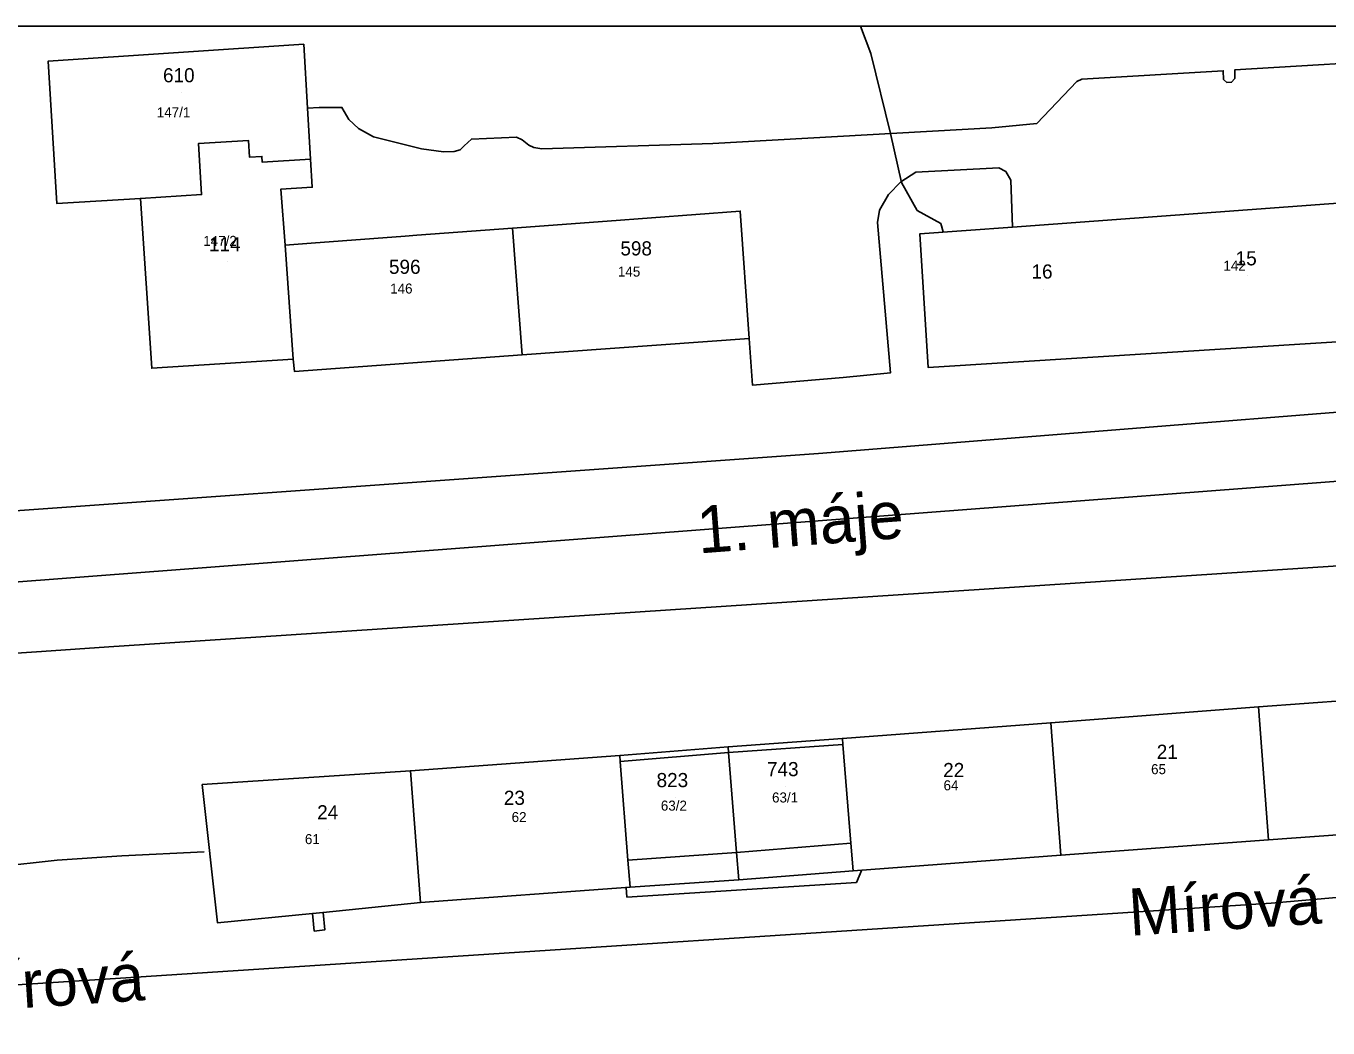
# Model space of a CAD drawing. Extents: x -873642 to -872917, y -1012962 to -1012567.
# Drawn here: x -873283.8 to -873173.4, y -1012652.4 to -1012567.5 of the extents above; entities that cross this region are included whole.
import ezdxf

# ---------------------------------------------------------------- set-up
doc = ezdxf.new("R2010")
doc.units = 0
for name, color, linetype in [('adresni_misto', 7, 'Continuous'), ('cisla_parcelni_kn', 7, 'Continuous'), ('cislo_domovni', 7, 'Continuous'), ('osy_ulic', 7, 'Continuous'), ('parcely_kn', 7, 'Continuous'), ('stavebni_objekty_bydleni', 7, 'Continuous'), ('TRASY - zamereno', 7, 'Continuous'), ('ulice', 7, 'Continuous')]:
    doc.layers.add(name, color=color, linetype=linetype)

msp = doc.modelspace()

# ---------------------------------------------------------------- linework, layer by layer
at = {"layer": 'adresni_misto'}
for p, q in [((-873270.54, -1012573.17), (-873270.54, -1012573.17)), ((-873266.64, -1012587.5), (-873266.64, -1012587.5)), ((-873231.76, -1012587.85), (-873231.76, -1012587.85)), ((-873180.19, -1012588.69), (-873180.19, -1012588.69)), ((-873251.38, -1012589.41), (-873251.38, -1012589.41)), ((-873197.5, -1012589.81), (-873197.5, -1012589.81)), ((-873186.88, -1012630.53), (-873186.88, -1012630.53)), ((-873228.69, -1012632.93), (-873228.69, -1012632.93)), ((-873219.33, -1012632), (-873219.33, -1012632)), ((-873204.99, -1012632.08), (-873204.99, -1012632.08)), ((-873242.24, -1012634.43), (-873242.24, -1012634.43)), ((-873258.07, -1012635.66), (-873258.07, -1012635.66))]:
    msp.add_line(p, q, dxfattribs=at)
at = {"layer": 'osy_ulic'}
for points in [[(-872916.93, -1012586.66), (-872957.62, -1012590.24), (-872977.73, -1012591.46), (-872994.83, -1012592.51), (-873031.96, -1012595.34), (-873059.56, -1012597.3), (-873096.52, -1012600.28), (-873281.07, -1012614.36), (-873481.95, -1012629.68)], [(-873478.28, -1012662.13), (-873469.53, -1012661.58), (-873334.68, -1012652.02), (-873276.17, -1012648.25), (-873178.17, -1012641.86), (-873066.08, -1012632.13)]]:
    msp.add_lwpolyline(points, dxfattribs=at)
at = {"layer": 'parcely_kn'}
msp.add_line((-873158.58, -1012567.5), (-873319.68, -1012567.5), dxfattribs=at)
msp.add_line((-873158.58, -1012567.5), (-873319.68, -1012567.5), dxfattribs=at)
for points in [[(-873259.63, -1012578.8), (-873263.72, -1012579.05), (-873263.76, -1012578.55), (-873264.81, -1012578.61), (-873264.9, -1012577.19), (-873269.13, -1012577.45), (-873268.87, -1012581.79), (-873274.05, -1012582.11), (-873281.15, -1012582.54), (-873281.88, -1012570.48), (-873260.21, -1012569.04), (-873259.89, -1012574.46)], [(-873259.63, -1012578.8), (-873263.72, -1012579.05), (-873263.76, -1012578.55), (-873264.81, -1012578.61), (-873264.9, -1012577.19), (-873269.13, -1012577.45), (-873268.87, -1012581.79), (-873274.05, -1012582.11), (-873281.15, -1012582.54), (-873281.88, -1012570.48), (-873260.21, -1012569.04), (-873259.89, -1012574.46)], [(-873259.63, -1012578.8), (-873259.49, -1012581.17), (-873262.15, -1012581.33), (-873261.79, -1012586.08), (-873261.11, -1012595.73), (-873273.1, -1012596.52), (-873274.05, -1012582.11), (-873268.87, -1012581.79), (-873269.13, -1012577.45), (-873264.9, -1012577.19), (-873264.81, -1012578.61), (-873263.76, -1012578.55), (-873263.72, -1012579.05)], [(-873259.63, -1012578.8), (-873259.49, -1012581.17), (-873262.15, -1012581.33), (-873261.79, -1012586.08), (-873261.11, -1012595.73), (-873273.1, -1012596.52), (-873274.05, -1012582.11), (-873268.87, -1012581.79), (-873269.13, -1012577.45), (-873264.9, -1012577.19), (-873264.81, -1012578.61), (-873263.76, -1012578.55), (-873263.72, -1012579.05)], [(-873155.02, -1012581.21), (-873154.13, -1012593.11), (-873207.27, -1012596.44), (-873207.98, -1012585.12), (-873200.1, -1012584.54), (-873162.95, -1012581.8)], [(-873155.02, -1012581.21), (-873154.13, -1012593.11), (-873207.27, -1012596.44), (-873207.98, -1012585.12), (-873200.1, -1012584.54), (-873162.95, -1012581.8)], [(-873242.5, -1012584.64), (-873234.47, -1012584.03), (-873223.19, -1012583.19), (-873222.44, -1012593.98), (-873241.69, -1012595.39)], [(-873242.5, -1012584.64), (-873234.47, -1012584.03), (-873223.19, -1012583.19), (-873222.44, -1012593.98), (-873241.69, -1012595.39)], [(-873261.79, -1012586.08), (-873259.58, -1012585.91), (-873251.62, -1012585.32), (-873250.61, -1012585.24), (-873242.5, -1012584.64), (-873241.69, -1012595.39), (-873260.98, -1012596.8), (-873261.11, -1012595.73)], [(-873261.79, -1012586.08), (-873259.58, -1012585.91), (-873251.62, -1012585.32), (-873250.61, -1012585.24), (-873242.5, -1012584.64), (-873241.69, -1012595.39), (-873260.98, -1012596.8), (-873261.11, -1012595.73)], [(-873169.13, -1012635.82), (-873169.03, -1012637.22), (-873170.1, -1012637.3), (-873170.2, -1012635.91), (-873178.41, -1012636.51), (-873179.26, -1012625.23), (-873171.5, -1012624.65), (-873171.53, -1012624.2), (-873169.44, -1012624.04), (-873169.41, -1012624.49), (-873161.65, -1012623.9), (-873160.8, -1012635.21)], [(-873169.13, -1012635.82), (-873169.03, -1012637.22), (-873170.1, -1012637.3), (-873170.2, -1012635.91), (-873178.41, -1012636.51), (-873179.26, -1012625.23), (-873171.5, -1012624.65), (-873171.53, -1012624.2), (-873169.44, -1012624.04), (-873169.41, -1012624.49), (-873161.65, -1012623.9), (-873160.8, -1012635.21)], [(-873196.87, -1012626.57), (-873179.26, -1012625.23), (-873178.41, -1012636.51), (-873196.01, -1012637.81)], [(-873196.87, -1012626.57), (-873179.26, -1012625.23), (-873178.41, -1012636.51), (-873196.01, -1012637.81)], [(-873214.53, -1012627.9), (-873196.87, -1012626.57), (-873196.01, -1012637.81), (-873213.62, -1012639.12), (-873213.81, -1012636.78), (-873214.49, -1012628.4)], [(-873214.53, -1012627.9), (-873196.87, -1012626.57), (-873196.01, -1012637.81), (-873213.62, -1012639.12), (-873213.81, -1012636.78), (-873214.49, -1012628.4)], [(-873213.62, -1012639.12), (-873223.33, -1012639.88), (-873223.51, -1012637.58), (-873224.18, -1012629.09), (-873224.21, -1012628.62), (-873214.53, -1012627.9), (-873214.49, -1012628.4), (-873213.81, -1012636.78)], [(-873213.62, -1012639.12), (-873223.33, -1012639.88), (-873223.51, -1012637.58), (-873224.18, -1012629.09), (-873224.21, -1012628.62), (-873214.53, -1012627.9), (-873214.49, -1012628.4), (-873213.81, -1012636.78)], [(-873251.16, -1012630.64), (-873233.42, -1012629.35), (-873233.38, -1012629.85), (-873232.72, -1012638.23), (-873232.54, -1012640.52), (-873250.31, -1012641.82)], [(-873251.16, -1012630.64), (-873233.42, -1012629.35), (-873233.38, -1012629.85), (-873232.72, -1012638.23), (-873232.54, -1012640.52), (-873250.31, -1012641.82)], [(-873233.42, -1012629.35), (-873224.21, -1012628.62), (-873224.18, -1012629.09), (-873223.51, -1012637.58), (-873223.33, -1012639.88), (-873232.54, -1012640.52), (-873232.72, -1012638.23), (-873233.38, -1012629.85)], [(-873233.42, -1012629.35), (-873224.21, -1012628.62), (-873224.18, -1012629.09), (-873223.51, -1012637.58), (-873223.33, -1012639.88), (-873232.54, -1012640.52), (-873232.72, -1012638.23), (-873233.38, -1012629.85)], [(-873250.31, -1012641.82), (-873258.57, -1012642.65), (-873258.42, -1012644.14), (-873259.32, -1012644.23), (-873259.47, -1012642.74), (-873267.51, -1012643.54), (-873268.81, -1012631.81), (-873251.16, -1012630.64)], [(-873250.31, -1012641.82), (-873258.57, -1012642.65), (-873258.42, -1012644.14), (-873259.32, -1012644.23), (-873259.47, -1012642.74), (-873267.51, -1012643.54), (-873268.81, -1012631.81), (-873251.16, -1012630.64)]]:
    msp.add_lwpolyline(points, close=True, dxfattribs=at)
for points in [[(-873154.13, -1012593.11), (-873207.27, -1012596.44), (-873207.98, -1012585.12), (-873200.1, -1012584.54), (-873200.25, -1012580.58), (-873200.67, -1012579.84), (-873201.28, -1012579.52), (-873208.31, -1012579.89), (-873209.58, -1012580.71), (-873210.64, -1012581.78), (-873211.4, -1012583.11), (-873211.56, -1012584.16), (-873210.46, -1012596.91), (-873214.48, -1012597.3), (-873222.15, -1012597.96), (-873222.44, -1012593.98), (-873241.69, -1012595.39), (-873260.98, -1012596.8), (-873261.11, -1012595.73), (-873273.1, -1012596.52), (-873274.05, -1012582.11), (-873281.15, -1012582.54), (-873281.88, -1012570.48), (-873260.21, -1012569.04), (-873259.89, -1012574.46), (-873258.9, -1012574.41), (-873256.97, -1012574.4), (-873256.39, -1012575.41), (-873255.56, -1012576.2), (-873254.3, -1012576.89), (-873250.21, -1012577.9), (-873248.35, -1012578.17), (-873247.44, -1012578.13), (-873246.95, -1012578), (-873246.61, -1012577.67), (-873245.99, -1012577.08), (-873242.17, -1012576.92), (-873241.7, -1012577.15), (-873241.12, -1012577.61), (-873240.71, -1012577.81), (-873240.03, -1012577.91), (-873225.53, -1012577.46), (-873201.86, -1012576.14), (-873198.05, -1012575.75), (-873194.65, -1012572.2), (-873194.24, -1012572), (-873182.24, -1012571.29), (-873182.21, -1012572.04), (-873181.93, -1012572.29), (-873181.53, -1012572.27), (-873181.27, -1012571.95), (-873181.27, -1012571.22), (-873165.19, -1012570.24)], [(-873154.13, -1012593.11), (-873207.27, -1012596.44), (-873207.98, -1012585.12), (-873200.1, -1012584.54), (-873200.25, -1012580.58), (-873200.67, -1012579.84), (-873201.28, -1012579.52), (-873208.31, -1012579.89), (-873209.58, -1012580.71), (-873210.64, -1012581.78), (-873211.4, -1012583.11), (-873211.56, -1012584.16), (-873210.46, -1012596.91), (-873214.48, -1012597.3), (-873222.15, -1012597.96), (-873222.44, -1012593.98), (-873241.69, -1012595.39), (-873260.98, -1012596.8), (-873261.11, -1012595.73), (-873273.1, -1012596.52), (-873274.05, -1012582.11), (-873281.15, -1012582.54), (-873281.88, -1012570.48), (-873260.21, -1012569.04), (-873259.89, -1012574.46), (-873258.9, -1012574.41), (-873256.97, -1012574.4), (-873256.39, -1012575.41), (-873255.56, -1012576.2), (-873254.3, -1012576.89), (-873250.21, -1012577.9), (-873248.35, -1012578.17), (-873247.44, -1012578.13), (-873246.95, -1012578), (-873246.61, -1012577.67), (-873245.99, -1012577.08), (-873242.17, -1012576.92), (-873241.7, -1012577.15), (-873241.12, -1012577.61), (-873240.71, -1012577.81), (-873240.03, -1012577.91), (-873225.53, -1012577.46), (-873201.86, -1012576.14), (-873198.05, -1012575.75), (-873194.65, -1012572.2), (-873194.24, -1012572), (-873182.24, -1012571.29), (-873182.21, -1012572.04), (-873181.93, -1012572.29), (-873181.53, -1012572.27), (-873181.27, -1012571.95), (-873181.27, -1012571.22), (-873165.19, -1012570.24)], [(-873165.19, -1012570.24), (-873181.27, -1012571.22), (-873181.27, -1012571.95), (-873181.53, -1012572.27), (-873181.93, -1012572.29), (-873182.21, -1012572.04), (-873182.24, -1012571.29), (-873194.24, -1012572), (-873194.65, -1012572.2), (-873198.05, -1012575.75), (-873201.86, -1012576.14), (-873225.53, -1012577.46), (-873240.03, -1012577.91), (-873240.71, -1012577.81), (-873241.12, -1012577.61), (-873241.7, -1012577.15), (-873242.17, -1012576.92), (-873245.99, -1012577.08), (-873246.61, -1012577.67), (-873246.95, -1012578), (-873247.44, -1012578.13), (-873248.35, -1012578.17), (-873250.21, -1012577.9), (-873254.3, -1012576.89), (-873255.56, -1012576.2), (-873256.39, -1012575.41), (-873256.97, -1012574.4), (-873258.9, -1012574.41), (-873259.89, -1012574.46), (-873259.63, -1012578.8), (-873259.49, -1012581.17), (-873262.15, -1012581.33), (-873261.79, -1012586.08), (-873259.58, -1012585.91), (-873251.62, -1012585.32), (-873250.61, -1012585.24), (-873242.5, -1012584.64), (-873234.47, -1012584.03), (-873223.19, -1012583.19), (-873222.44, -1012593.98), (-873222.15, -1012597.96), (-873214.48, -1012597.3), (-873210.46, -1012596.91), (-873211.56, -1012584.16), (-873211.4, -1012583.11), (-873210.64, -1012581.78), (-873209.58, -1012580.71), (-873208.31, -1012579.89), (-873201.28, -1012579.52), (-873200.67, -1012579.84), (-873200.25, -1012580.58), (-873200.1, -1012584.54), (-873162.95, -1012581.8)], [(-873165.19, -1012570.24), (-873181.27, -1012571.22), (-873181.27, -1012571.95), (-873181.53, -1012572.27), (-873181.93, -1012572.29), (-873182.21, -1012572.04), (-873182.24, -1012571.29), (-873194.24, -1012572), (-873194.65, -1012572.2), (-873198.05, -1012575.75), (-873201.86, -1012576.14), (-873225.53, -1012577.46), (-873240.03, -1012577.91), (-873240.71, -1012577.81), (-873241.12, -1012577.61), (-873241.7, -1012577.15), (-873242.17, -1012576.92), (-873245.99, -1012577.08), (-873246.61, -1012577.67), (-873246.95, -1012578), (-873247.44, -1012578.13), (-873248.35, -1012578.17), (-873250.21, -1012577.9), (-873254.3, -1012576.89), (-873255.56, -1012576.2), (-873256.39, -1012575.41), (-873256.97, -1012574.4), (-873258.9, -1012574.41), (-873259.89, -1012574.46), (-873259.63, -1012578.8), (-873259.49, -1012581.17), (-873262.15, -1012581.33), (-873261.79, -1012586.08), (-873259.58, -1012585.91), (-873251.62, -1012585.32), (-873250.61, -1012585.24), (-873242.5, -1012584.64), (-873234.47, -1012584.03), (-873223.19, -1012583.19), (-873222.44, -1012593.98), (-873222.15, -1012597.96), (-873214.48, -1012597.3), (-873210.46, -1012596.91), (-873211.56, -1012584.16), (-873211.4, -1012583.11), (-873210.64, -1012581.78), (-873209.58, -1012580.71), (-873208.31, -1012579.89), (-873201.28, -1012579.52), (-873200.67, -1012579.84), (-873200.25, -1012580.58), (-873200.1, -1012584.54), (-873162.95, -1012581.8)], [(-873143.44, -1012597.91), (-873216.55, -1012603.73), (-873279.94, -1012608.27), (-873348.3, -1012613.15), (-873406.66, -1012617.85), (-873469.84, -1012622.48), (-873491.33, -1012623.66), (-873566.46, -1012629.92), (-873583.11, -1012630.93), (-873584.28, -1012631.65), (-873606.27, -1012634.41), (-873608.98, -1012633.05), (-873615.37, -1012633.09), (-873642.29, -1012633.96)], [(-873348.3, -1012613.15), (-873279.94, -1012608.27), (-873216.55, -1012603.73), (-873143.44, -1012597.91)], [(-873348.3, -1012613.15), (-873279.94, -1012608.27), (-873216.55, -1012603.73), (-873143.44, -1012597.91)], [(-873642.29, -1012646.91), (-873615.37, -1012644.94), (-873586.69, -1012643.34), (-873548.73, -1012640.58), (-873509.03, -1012637.61), (-873492.26, -1012636.3), (-873470.15, -1012634.51), (-873407.08, -1012629.93), (-873286.69, -1012620.81), (-873282.45, -1012620.53), (-873276.73, -1012620.14), (-873273.72, -1012619.94), (-873079.43, -1012607.12)], [(-873407.08, -1012629.93), (-873286.69, -1012620.81), (-873282.45, -1012620.53), (-873276.73, -1012620.14), (-873273.72, -1012619.94), (-873079.43, -1012607.12)], [(-873407.08, -1012629.93), (-873286.69, -1012620.81), (-873282.45, -1012620.53), (-873276.73, -1012620.14), (-873273.72, -1012619.94), (-873079.43, -1012607.12)], [(-873171.5, -1012624.65), (-873179.26, -1012625.23), (-873196.87, -1012626.57), (-873214.53, -1012627.9), (-873224.21, -1012628.62), (-873233.42, -1012629.35), (-873251.16, -1012630.64), (-873268.81, -1012631.81), (-873267.51, -1012643.54), (-873259.47, -1012642.74), (-873259.32, -1012644.23), (-873258.42, -1012644.14), (-873258.57, -1012642.65), (-873250.31, -1012641.82), (-873232.54, -1012640.52), (-873223.33, -1012639.88), (-873213.62, -1012639.12), (-873196.01, -1012637.81), (-873178.41, -1012636.51), (-873170.2, -1012635.91)], [(-873171.5, -1012624.65), (-873179.26, -1012625.23), (-873196.87, -1012626.57), (-873214.53, -1012627.9), (-873224.21, -1012628.62), (-873233.42, -1012629.35), (-873251.16, -1012630.64), (-873268.81, -1012631.81), (-873267.51, -1012643.54), (-873259.47, -1012642.74), (-873259.32, -1012644.23), (-873258.42, -1012644.14), (-873258.57, -1012642.65), (-873250.31, -1012641.82), (-873232.54, -1012640.52), (-873223.33, -1012639.88), (-873213.62, -1012639.12), (-873196.01, -1012637.81), (-873178.41, -1012636.51), (-873170.2, -1012635.91)]]:
    msp.add_lwpolyline(points, dxfattribs=at)
at = {"layer": 'stavebni_objekty_bydleni'}
for points in [[(-873281.88, -1012570.48), (-873260.21, -1012569.04), (-873259.89, -1012574.46), (-873259.63, -1012578.8), (-873263.72, -1012579.05), (-873263.76, -1012578.55), (-873264.81, -1012578.61), (-873264.9, -1012577.19), (-873269.13, -1012577.45), (-873268.87, -1012581.79), (-873274.05, -1012582.11), (-873281.15, -1012582.54)], [(-873274.05, -1012582.11), (-873268.87, -1012581.79), (-873269.13, -1012577.45), (-873264.9, -1012577.19), (-873264.81, -1012578.61), (-873263.76, -1012578.55), (-873263.72, -1012579.05), (-873259.63, -1012578.8), (-873259.49, -1012581.17), (-873262.15, -1012581.33), (-873261.79, -1012586.08), (-873261.11, -1012595.73), (-873273.1, -1012596.52)], [(-873154.13, -1012593.11), (-873207.27, -1012596.44), (-873207.98, -1012585.12), (-873200.1, -1012584.54), (-873162.95, -1012581.8), (-873155.02, -1012581.21)], [(-873242.5, -1012584.64), (-873234.47, -1012584.03), (-873223.19, -1012583.19), (-873222.44, -1012593.98), (-873241.69, -1012595.39)], [(-873251.62, -1012585.32), (-873250.61, -1012585.24), (-873242.5, -1012584.64), (-873241.69, -1012595.39), (-873260.98, -1012596.8), (-873261.11, -1012595.73), (-873261.79, -1012586.08), (-873259.58, -1012585.91)], [(-873161.65, -1012623.9), (-873160.8, -1012635.21), (-873169.13, -1012635.82), (-873170.2, -1012635.91), (-873178.41, -1012636.51), (-873179.26, -1012625.23), (-873171.5, -1012624.65), (-873169.41, -1012624.49)], [(-873196.01, -1012637.81), (-873196.87, -1012626.57), (-873179.26, -1012625.23), (-873178.41, -1012636.51)], [(-873213.62, -1012639.12), (-873213.81, -1012636.78), (-873214.49, -1012628.4), (-873214.53, -1012627.9), (-873196.87, -1012626.57), (-873196.01, -1012637.81)], [(-873224.18, -1012629.09), (-873214.49, -1012628.4), (-873213.81, -1012636.78), (-873223.51, -1012637.58)], [(-873233.42, -1012629.35), (-873233.38, -1012629.85), (-873232.72, -1012638.23), (-873232.54, -1012640.52), (-873250.31, -1012641.82), (-873251.16, -1012630.64)], [(-873224.18, -1012629.09), (-873223.51, -1012637.58), (-873232.72, -1012638.23), (-873233.38, -1012629.85)], [(-873267.51, -1012643.54), (-873268.81, -1012631.81), (-873251.16, -1012630.64), (-873250.31, -1012641.82), (-873258.57, -1012642.65), (-873259.47, -1012642.74)]]:
    msp.add_lwpolyline(points, close=True, dxfattribs=at)
at = {"layer": 'TRASY - zamereno'}
for p, q in [((-873213.01, -1012567.5), (-873212.11, -1012569.84)), ((-873212.11, -1012569.84), (-873210.45, -1012576.61)), ((-873210.45, -1012576.61), (-873209.53, -1012580.77)), ((-873209.53, -1012580.77), (-873208.19, -1012583.14)), ((-873208.19, -1012583.14), (-873206.18, -1012584.23)), ((-873206.18, -1012584.23), (-873205.99, -1012584.95)), ((-873288.5, -1012639.01), (-873281.11, -1012638.23)), ((-873281.11, -1012638.23), (-873275.64, -1012637.84)), ((-873275.64, -1012637.84), (-873268.65, -1012637.51)), ((-873213.33, -1012640.12), (-873212.88, -1012639.04)), ((-873232.86, -1012640.53), (-873232.8, -1012641.36)), ((-873232.8, -1012641.36), (-873213.33, -1012640.12))]:
    msp.add_line(p, q, dxfattribs=at)

# ---------------------------------------------------------------- texts
at = {"layer": 'cisla_parcelni_kn'}
for s, p in [('147/1', (-873272.67, -1012575.24)), ('147/1', (-873272.67, -1012575.24)), ('147/2', (-873268.73, -1012586.14)), ('147/2', (-873268.73, -1012586.14)), ('142', (-873182.23, -1012588.24)), ('142', (-873182.23, -1012588.24)), ('145', (-873233.57, -1012588.74)), ('145', (-873233.57, -1012588.74)), ('146', (-873252.88, -1012590.18)), ('146', (-873252.88, -1012590.18)), ('65', (-873188.36, -1012630.93)), ('65', (-873188.36, -1012630.93)), ('64', (-873205.96, -1012632.3)), ('64', (-873205.96, -1012632.3)), ('63/1', (-873220.5, -1012633.33)), ('63/1', (-873220.5, -1012633.33)), ('63/2', (-873229.93, -1012634.02)), ('63/2', (-873229.93, -1012634.02)), ('62', (-873242.58, -1012634.99)), ('62', (-873242.58, -1012634.99)), ('61', (-873260.11, -1012636.86)), ('61', (-873260.11, -1012636.86))]:
    msp.add_text(s, height=0.85, dxfattribs=at).set_placement(p)
at = {"layer": 'cislo_domovni'}
for s, p in [('610', (-873272.14, -1012572.27)), ('114', (-873268.24, -1012586.6)), ('598', (-873233.36, -1012586.95)), ('596', (-873252.98, -1012588.51)), ('15', (-873181.19, -1012587.79)), ('16', (-873198.5, -1012588.91)), ('21', (-873187.88, -1012629.63)), ('743', (-873220.93, -1012631.1)), ('22', (-873205.99, -1012631.18)), ('823', (-873230.29, -1012632.03)), ('23', (-873243.24, -1012633.53)), ('24', (-873259.07, -1012634.76))]:
    msp.add_text(s, height=1.2, dxfattribs=at).set_placement(p)
at = {"layer": 'ulice'}
for s, rotation, p in [('1. máje', 4.3629, (-873226.71, -1012612.22)), ('Mírová', 3.7306, (-873190.14, -1012644.64)), ('Mírová', 3.6867, (-873289.93, -1012651.14))]:
    msp.add_text(s, height=4, rotation=rotation, dxfattribs=at).set_placement(p)

doc.saveas('drawing.dxf')
